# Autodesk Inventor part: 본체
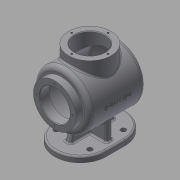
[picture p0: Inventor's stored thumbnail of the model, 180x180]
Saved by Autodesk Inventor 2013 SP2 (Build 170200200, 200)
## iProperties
Created: 2023-01
Part Number: 본체
Material: Generic
Document SubType Name: Modeling
Designer: i
Density: 1 g/cm^3
Author: i
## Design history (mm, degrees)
sketch "스케치1"
  geometry: L1 (-46, 34)-(-46, 0); L2 (46, 34)-(46, 0); L3 (0, 80)-(0, -46); A1 r 46 centre (0, 0) between (-46, 0) and (46, 0); A2 r 46 centre (0, 34) between (46, 34) and (-46, 34); 1 further point
  constraints: 6 end point, 6 point on circle, 4 tangent, 2 centre point, 2 coincident, 1 equal radius, 1 vertical alignment
  dimensions: "d10" = 92 diameter of A1; "d12" = 126 distance of L3.start L3.end
extrude "돌출1" new body sketch "스케치1" distance "d13" = 10; taper "d14" = 0 deg
node "작업 평면3"
  node "작업 평면2"
node "작업 평면4"
sketch "스케치9"
  geometry: L1 (-130, -34)-(-80, -34); L2 (-80, -34)-(-80, 76); L3 (-80, 76)-(-130, 76); L4 (-130, 76)-(-130, 65.087); L5 (0, 0)-(0, 0) reference; L6 (0, 0)-(-10, 0) reference; L7 (-10, 0)-(-10, 0) reference; L8 (0, 0)-(-10, 0) reference; L9 (0, 0)-(0, -46) reference; L10 (0, 0)-(0, 34) reference; L11 (0, 34)-(-10, 34) reference; L12 (-10, 0)-(-10, 34) reference; L13 (0, 0)-(-10, 0) reference; L14 (-16.796, 17)-(-185.396, 17); L15 (0, 0)-(0, 34) reference; L16 (-130, 65.087)-(-130, -34); L17 (-80, -29)-(-85.344, -29); L18 (-85.344, -29)-(-125, -29); L19 (-125, -29)-(-125, -24.092); L20 (-125, -24.092)-(-125, 61.83); L21 (-125, 61.83)-(-125, 76); A1 r 120 centre (-80, -44) between (-183.339, 17) and (-80, 76); A2 r 120 centre (-80, -44) between (-130, 65.087) and (-183.339, 17); A3 r 120 centre (-80, -44) between (-80, 76) and (-130, 65.087); A4 r 115 centre (-80, -44) between (-130, 59.562) and (-80, 71); A5 r 115 centre (-80, -44) between (-125, 61.83) and (-130, 59.562); A6 r 115 centre (-80, -44) between (-80, 71) and (-125, 61.83); 1 further point
  constraints: 22 end point, 12 point on circle, 7 point on line, 6 centre point, 6 parallel, 3 perpendicular, 2 tangent, 1 concentric, 1 horizontal, 1 horizontal alignment, 1 midpoint
  dimensions: "d51" = 80 distance from line of L9 L1.end; "d52" = 100 diameter of L4 L2; "d53" = 51 distance from line of L14 L1.start; "d56" = 59 distance from line of L14 L2.end; "d57" = 5 distance between parallel lines of L1 L18; "d58" = 5 distance between parallel lines of L16 L19; "d124" = 5 distance of L2.end A4.end; "d125" = 240 diameter of A3
revolve "회전1" sketch "스케치9" stored, may be unused: angle "d60" = 90 deg
sketch "스케치10"
  geometry: C1 r 50 at (0, 0) reference; C2 r 38 at (0, 0); 1 further point
  constraints: 1 centre point, 1 coincident
  dimensions: "d61" = 76 diameter of C2
extrude "돌출7" join sketch "스케치10" distance "d63" = 12; taper "d64" = 0 deg
sketch "스케치11"
  geometry: C1 r 38 at (0, 0) reference; C2 r 27 at (0, 0); 1 further point
  constraints: 1 centre point, 1 coincident
  dimensions: "d65" = 54 diameter of C2
extrude "돌출8" cut sketch "스케치11" distance "d67" = 17; taper "d68" = 0 deg
sketch "스케치8"
  geometry: L1 (-46, 34)-(-46, 0) reference; L2 (-35, 22)-(35, 22); L3 (35, 22)-(35, 12); L4 (35, 12)-(-35, 12); L5 (-35, 12)-(-35, 22); L6 (-46, 34)-(-46, 0) reference; L7 (46, 0)-(46, 34) reference; A1 r 46 centre (0, 34) between (46, 34) and (-46, 34) reference; A2 r 46 centre (0, 0) between (-46, 0) and (46, 0) reference; A3 r 46 centre (0, 34) between (46, 34) and (-46, 34) reference; 4 further points
  constraints: 8 end point, 3 midpoint, 2 parallel, 1 horizontal, 1 horizontal alignment, 1 perpendicular, 1 point on circle, 1 vertical alignment
  dimensions: "d45" = 70 distance of L2.start L2.end; "d47" = 10 distance of L4.end L2.start
extrude "돌출6" join sketch "스케치8" stored distance "d48" = 40; taper "d49" = 0 deg
sketch "스케치13" dims "d73" = 65
  geometry: C1 r 27 at (0, 0) reference; C2 r 38 at (0, 0) reference; 3 further points
  constraints: 2 vertical alignment, 1 coincident, 2 other
hole "구멍1" sketch "스케치13" at (0, 32.5) diameter "d75" = 3.242; stored, may be unused: countersink angle "d79" = 90 deg, drill point angle "d81" = 118 deg; dims "d76" = 8, "d77" = 4, "d78" = 2, "d80" = 10
node "작업 평면7"
sketch "스케치14"
  geometry: L1 (-46, 34)-(-46, 0) reference; L2 (46, 0)-(46, 34) reference; L3 (-35, 22)-(35, 22) reference; L4 (35, 22)-(35, 12) reference; L5 (35, 12)-(-35, 12) reference; L6 (-35, 12)-(-35, 22) reference; C1 r 38 at (0, 17); A1 r 46 centre (0, 0) between (-46, 0) and (46, 0) reference; A2 r 46 centre (0, 34) between (46, 34) and (-46, 34) reference; 3 further points
  constraints: 1 centre point, 1 horizontal alignment, 1 midpoint, 1 point on circle, 1 vertical alignment
  dimensions: "d86" = 76 diameter of C1
extrude "돌출9" join sketch "스케치14" stored distance "d89" = 90; taper "d90" = 0 deg
sketch "스케치15"
  geometry: C1 r 38 at (0, 0) reference; C2 r 27 at (0, 0); 1 further point
  constraints: 1 centre point, 1 coincident
  dimensions: "d91" = 54 diameter of C2
extrude "돌출10" cut sketch "스케치15" distance "d93" = 50; taper "d94" = 0 deg
sketch "스케치16" dims "d95" = 65
  geometry: C1 r 27 at (0, 0) reference; C2 r 38 at (0, 0) reference; 3 further points
  constraints: 2 vertical alignment, 1 coincident, 2 other
hole "구멍2" sketch "스케치16" at (0, 32.5) diameter "d97" = 3.242; stored, may be unused: countersink angle "d101" = 90 deg, drill point angle "d103" = 118 deg; dims "d98" = 8, "d99" = 4, "d100" = 2, "d102" = 10
chamfer "모따기1" distance "d107" = 1; stored, may be unused: second distance "d108" = 2, angle "d109" = 45 deg
sketch "스케치17"
  geometry: L1 (-35, -16.301)-(-10, -23); L2 (-10, -23)-(-10, 57); L3 (-10, 57)-(-35, 50.301); L4 (-35, 50.301)-(-35, -16.301); L5 (0, 0)-(0, -46); L6 (0, 0)-(0, 34) reference; L7 (0, 34)-(-10, 34) reference; L8 (-10, 0)-(-10, 34) reference; L9 (0, 0)-(-10, 0) reference; L10 (-10, 0)-(-10, 34) reference; 2 further points
  constraints: 10 end point, 2 midpoint, 2 parallel, 1 coincident, 1 equal length, 1 vertical
  dimensions: "d116" = 105 deg angle of L2 L1; "d117" = 25 distance between parallel lines of L2 L4; "d119" = 80 distance of L1.end L2.end; "d120" = 46 distance of L5.start L5.end; "d121" = 23 vertical distance of L5.end L1.end
extrude "돌출11" join sketch "스케치17" stored distance "d122" = 10; taper "d123" = 0 deg
fillet "모깎기1" dims "d126" = 8
fillet "모깎기2" dims "d127" = 3
fillet "모깎기3" dims "d128" = 3
sketch "스케치18"
  geometry: L1 (2, 59.302)-(-2, 59.302) reference; L2 (38, 15)-(38, 19) reference; L3 (-2, -25.302)-(2, -25.302) reference; L4 (-38, 19)-(-38, 15) reference; L5 (0, -25.302)-(0, 59.302); L6 (-38, 17)-(38, 17); 5 further points
  constraints: 4 end point, 4 midpoint
  dimensions: "d129" = 30 horizontal distance of L5.start point (30, -13); "d131" = 30 distance from line of L6 point (30, -13)
hole "구멍3" sketch "스케치18" at (30, -13) diameter "d132" = 9; stored, may be unused: countersink angle "d136" = 90 deg, drill point angle "d138" = 0 deg; dims "d133" = 8, "d134" = 4, "d135" = 2, "d137" = 10
node "작업 평면9"
sketch "스케치19"
  geometry: L1 (-61.544, 38)-(-61.544, -38) reference; L2 (-49.544, -38)-(-49.544, 38) reference; 2 further points
  constraints: 1 other
  dimensions: "d145" = 63 distance from line of L1 point (1.456, 0); "d146" = 80 vertical distance of point (-15.544, -80) point (1.456, 0)
feature "엠보싱1" sketch "스케치19" dims "d147" = 0.5, "d148" = 0
node "솔리드1"
pattern_circular "원형 패턴1" dims angle "d83" = 360 deg
pattern_circular "원형 패턴2" dims angle "d105" = 360 deg
pattern_linear "직사각형 패턴1" dims "d141" = 60
node "투영된 루프3"
node "투영된 루프4"
node "투영된 루프5"
node "투영된 루프7"
node "투영된 루프9"
node "투영된 루프10"
other parameters: "d22" = 63, "d39" = -46, "d85" = 134
